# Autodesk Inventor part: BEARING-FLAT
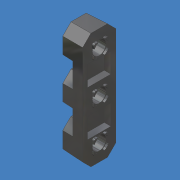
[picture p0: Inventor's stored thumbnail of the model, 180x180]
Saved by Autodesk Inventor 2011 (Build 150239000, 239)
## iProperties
Created: 2007-08
Part Number: BEARING-FLAT
Material: Delrin, Black
Document SubType Name: Modeling
Density: 1.425 g/cm^3
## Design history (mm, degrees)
feature "Base1"
body "Solid1"
